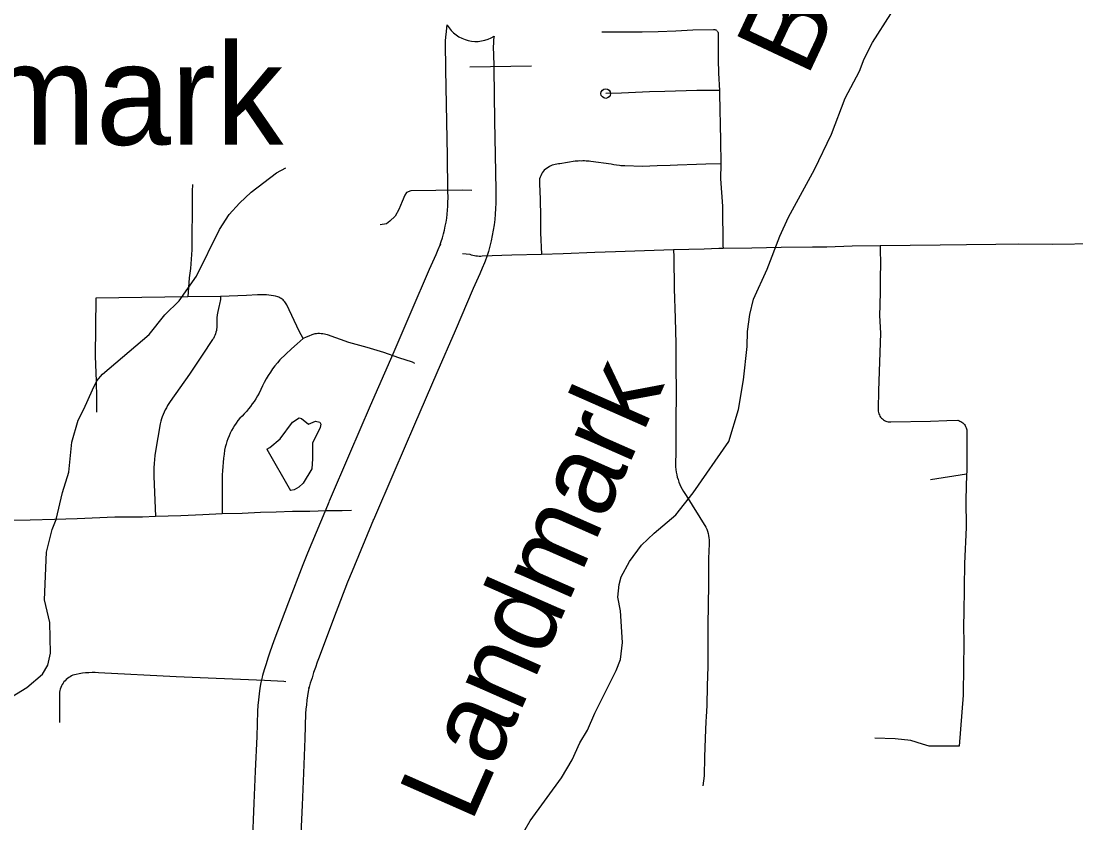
# Model space of a CAD drawing. Extents: x -19 to 366, y -4 to 359.
# Drawn here: x 152.307 to 153.352, y 181.159 to 181.952 of the extents above; entities that cross this region are included whole.
import ezdxf

# ---------------------------------------------------------------- set-up
doc = ezdxf.new("R2010")
doc.units = 0
for name, color, linetype in [('Level 10', 7, 'Continuous'), ('Level 24', 7, 'Continuous'), ('Level 31', 7, 'Continuous'), ('Level 35', 7, 'Continuous'), ('Level 60', 7, 'Continuous')]:
    doc.layers.add(name, color=color, linetype=linetype)

msp = doc.modelspace()

# ---------------------------------------------------------------- linework, layer by layer
at = {"layer": 'Level 10'}
for p, q in [((152.7752, 181.9088), (152.7752, 181.9088)), ((152.7772, 181.7846), (152.7772, 181.7846)), ((152.7225, 181.7313), (152.7218, 181.7296)), ((152.7667, 181.7144), (152.766, 181.7127)), ((152.7189, 181.6039), (152.7189, 181.6039)), ((152.6562, 181.4589), (152.6351, 181.4076)), ((152.6561, 181.4586), (152.6562, 181.4589)), ((152.6351, 181.4076), (152.6351, 181.4076)), ((152.5462, 181.3029), (152.5466, 181.3048)), ((152.5921, 181.2915), (152.5926, 181.2934))]:
    msp.add_line(p, q, dxfattribs=at)
for points in [[(152.7279, 181.9078), (152.7275, 181.9272), (152.7276, 181.932), (152.7279, 181.9366), (152.7283, 181.9413), (152.7289, 181.9458), (152.7292, 181.9482)], [(152.7755, 181.9371), (152.7754, 181.9361), (152.7751, 181.9331), (152.7749, 181.9299), (152.7748, 181.927), (152.7752, 181.9088)], [(152.7299, 181.784), (152.7294, 181.8187), (152.7287, 181.8524), (152.7279, 181.9042), (152.7279, 181.9077)], [(152.7752, 181.9088), (152.7753, 181.905), (152.776, 181.8533), (152.7768, 181.8196), (152.7772, 181.7846)], [(152.7218, 181.7296), (152.7232, 181.7338), (152.7245, 181.7376), (152.7255, 181.7414), (152.7265, 181.7452), (152.7273, 181.7491), (152.728, 181.7531), (152.7287, 181.757), (152.7291, 181.761), (152.7295, 181.765), (152.7298, 181.7689), (152.7299, 181.7729), (152.73, 181.777), (152.7299, 181.784)], [(152.7772, 181.7846), (152.7773, 181.7772), (152.7773, 181.7719), (152.7771, 181.7665), (152.7767, 181.7611), (152.7762, 181.7558), (152.7756, 181.7504), (152.7747, 181.7451), (152.7737, 181.7399), (152.7726, 181.7346), (152.7713, 181.7294), (152.7699, 181.7241), (152.7683, 181.7191), (152.7667, 181.7144)], [(152.6755, 181.6228), (152.6935, 181.6642), (152.7115, 181.7066), (152.7181, 181.7209), (152.7202, 181.7259), (152.7225, 181.7313)], [(152.766, 181.7127), (152.7638, 181.7076), (152.7615, 181.7019), (152.7547, 181.6874), (152.737, 181.6455), (152.7189, 181.6039)], [(152.6126, 181.4773), (152.6327, 181.5242), (152.6533, 181.5717), (152.6755, 181.6228)], [(152.7189, 181.6039), (152.6967, 181.5528), (152.6762, 181.5055), (152.6561, 181.4586)], [(152.5913, 181.4257), (152.6125, 181.477)], [(152.5466, 181.3048), (152.5483, 181.3105), (152.5501, 181.3163), (152.5519, 181.322), (152.5539, 181.3278), (152.5559, 181.3335), (152.5579, 181.3391), (152.5722, 181.3774), (152.5866, 181.4144), (152.5913, 181.4257)], [(152.6351, 181.4076), (152.6306, 181.3967), (152.6165, 181.3605), (152.6023, 181.3227), (152.6005, 181.3176), (152.5987, 181.3124), (152.5969, 181.3073), (152.5953, 181.3021), (152.5936, 181.2968), (152.5921, 181.2915)], [(152.5278, 181.0853), (152.5331, 181.1033), (152.5343, 181.111), (152.5355, 181.1252), (152.5365, 181.1365), (152.5381, 181.1782), (152.5395, 181.2098), (152.5409, 181.244), (152.5417, 181.2691), (152.5421, 181.2748), (152.5426, 181.2805), (152.5432, 181.2862), (152.5441, 181.292), (152.5451, 181.2976), (152.5462, 181.3029)], [(152.5926, 181.2934), (152.5916, 181.2887), (152.5908, 181.2843), (152.5902, 181.28), (152.5897, 181.2756), (152.5893, 181.2712), (152.589, 181.2668), (152.5882, 181.2423), (152.5868, 181.2078), (152.5854, 181.1762), (152.5837, 181.1336), (152.5827, 181.1213), (152.5814, 181.1052), (152.5793, 181.0928), (152.5732, 181.072)]]:
    msp.add_lwpolyline(points, dxfattribs=at)
msp.add_arc((152.7578, 181.9652), 0.0333, 210.8117, 302.1366, dxfattribs=at)
at = {"layer": 'Level 31'}
msp.add_line((152.7516, 181.9069), (152.8125, 181.9077), dxfattribs=at)
for points in [[(152.9961, 181.9426), (152.9956, 181.9429), (152.9951, 181.9432), (152.9946, 181.9434), (152.994, 181.9435), (152.9934, 181.9435), (152.9928, 181.9435), (152.9723, 181.943), (152.9554, 181.9422), (152.9379, 181.9415), (152.9221, 181.9412), (152.9073, 181.9409), (152.8823, 181.9409)], [(152.9961, 181.9426), (152.9965, 181.9422), (152.9969, 181.9417), (152.9971, 181.9411), (152.9973, 181.9406), (152.9974, 181.94), (152.9974, 181.914), (152.9978, 181.9006), (152.9986, 181.8835)], [(152.9986, 181.8835), (152.9762, 181.8832), (152.9446, 181.8825), (152.9294, 181.8821), (152.9017, 181.8806), (152.8861, 181.8803)], [(152.9986, 181.8835), (152.9988, 181.8801), (152.9996, 181.834), (153.0002, 181.8108)], [(153.0002, 181.8108), (152.9853, 181.8106), (152.976, 181.8101), (152.9571, 181.8093), (152.9498, 181.809), (152.9369, 181.8087), (152.9226, 181.8081), (152.9051, 181.8089), (152.9037, 181.8088), (152.901, 181.8089), (152.8997, 181.809), (152.8969, 181.8093), (152.8942, 181.8097), (152.8915, 181.8103), (152.8712, 181.8132), (152.8696, 181.8133), (152.8681, 181.8135), (152.8666, 181.8135), (152.865, 181.8136), (152.8635, 181.8136), (152.8619, 181.8135), (152.8604, 181.8136), (152.8589, 181.8135), (152.8573, 181.8134), (152.8558, 181.8133), (152.8407, 181.8109), (152.8392, 181.8107), (152.8377, 181.8105), (152.8362, 181.8102), (152.8347, 181.8098), (152.8332, 181.8093), (152.8304, 181.8081), (152.829, 181.8073), (152.8265, 181.8056), (152.8253, 181.8045), (152.8242, 181.8033), (152.8232, 181.802), (152.8228, 181.8013)], [(153.0002, 181.8108), (152.9999, 181.796), (153.0016, 181.769), (153.0021, 181.7296), (153.0023, 181.7272)], [(152.8228, 181.8013), (152.8224, 181.8005), (152.8217, 181.799), (152.8211, 181.7975), (152.8207, 181.7959), (152.8205, 181.7942), (152.8204, 181.7926), (152.8206, 181.7909), (152.8213, 181.7758), (152.8216, 181.7584), (152.8216, 181.7426), (152.8226, 181.7215)], [(152.4769, 181.7904), (152.4768, 181.7838), (152.4767, 181.7762), (152.4768, 181.7686), (152.4764, 181.7348), (152.4764, 181.7302), (152.4763, 181.7256), (152.4761, 181.721), (152.4758, 181.7164), (152.4754, 181.7118), (152.4749, 181.7072), (152.4744, 181.7027), (152.4737, 181.6981), (152.4725, 181.6793)], [(152.7535, 181.7843), (152.7439, 181.7848), (152.7179, 181.7843), (152.6933, 181.784), (152.6889, 181.7825), (152.6871, 181.7799), (152.6845, 181.7736), (152.6812, 181.7655), (152.6775, 181.7589), (152.6723, 181.7539), (152.6689, 181.7513), (152.6627, 181.7504)], [(152.8226, 181.7215), (152.844, 181.7221), (152.8752, 181.7234), (152.8957, 181.724), (152.9531, 181.7259)], [(152.9531, 181.7259), (152.9836, 181.7266), (152.9982, 181.7272), (153.0023, 181.7272)], [(152.9531, 181.7259), (152.9534, 181.7184), (152.9539, 181.6871), (152.9549, 181.6581), (152.9555, 181.6327), (152.9556, 181.608), (152.9558, 181.5877), (152.9554, 181.5524), (152.9554, 181.5209), (152.9551, 181.5184), (152.9551, 181.5158), (152.9551, 181.5133), (152.9553, 181.5108), (152.9555, 181.5082), (152.9559, 181.5057), (152.9564, 181.5032), (152.957, 181.5007), (152.9578, 181.4983), (152.9586, 181.4959), (152.9596, 181.4935), (152.9606, 181.4912), (152.9618, 181.4889), (152.9631, 181.4867), (152.9644, 181.4846), (152.9659, 181.4825), (152.9853, 181.4512), (152.9861, 181.4492), (152.9868, 181.4472), (152.9874, 181.4451), (152.9879, 181.443), (152.9882, 181.4408), (152.9885, 181.4387), (152.9886, 181.4365), (152.9886, 181.4343), (152.9884, 181.4322), (152.9881, 181.43), (152.9878, 181.4176), (152.988, 181.3946), (152.9872, 181.3543), (152.9872, 181.336), (152.9871, 181.3133), (152.9866, 181.2942), (152.9862, 181.2749), (152.9854, 181.2637), (152.9852, 181.259), (152.9845, 181.2426), (152.984, 181.2236), (152.9837, 181.2051), (152.9824, 181.1954)], [(153.0023, 181.7272), (153.0306, 181.7278), (153.0599, 181.7284), (153.0907, 181.7285), (153.105, 181.7288), (153.1301, 181.7295), (153.1579, 181.7299)], [(153.1579, 181.7299), (153.1578, 181.7252), (153.1583, 181.7128), (153.1579, 181.6972), (153.1578, 181.6844), (153.1576, 181.6709), (153.1573, 181.6608), (153.1582, 181.6433), (153.1562, 181.5862), (153.1558, 181.5684), (153.1558, 181.5672), (153.1559, 181.5659), (153.1561, 181.5646), (153.1565, 181.5634), (153.157, 181.5623), (153.1576, 181.5611), (153.1583, 181.5601), (153.1591, 181.5591), (153.1601, 181.5583), (153.1611, 181.5575), (153.1622, 181.5568), (153.1633, 181.5563), (153.1645, 181.5559), (153.1658, 181.5556), (153.167, 181.5554), (153.1683, 181.5554), (153.2076, 181.5563), (153.2238, 181.5569), (153.2346, 181.5571), (153.2357, 181.5568), (153.2368, 181.5563), (153.2378, 181.5558), (153.2388, 181.5552), (153.2397, 181.5544), (153.2405, 181.5536), (153.2413, 181.5527), (153.2419, 181.5518), (153.2424, 181.5508), (153.2429, 181.5497), (153.2433, 181.5486), (153.2435, 181.5475), (153.2437, 181.5463), (153.2437, 181.5451), (153.2435, 181.5061), (153.2434, 181.5037)], [(153.1579, 181.7299), (153.2172, 181.7307), (153.2432, 181.7309), (153.2722, 181.7314), (153.295, 181.7315), (153.3284, 181.7314), (153.3725, 181.7318)], [(152.7442, 181.722), (152.7515, 181.7214), (152.753, 181.7208), (152.7545, 181.7204), (152.7561, 181.72), (152.7576, 181.7197), (152.7592, 181.7196), (152.7607, 181.7195), (152.7623, 181.7195), (152.7639, 181.7197), (152.7933, 181.7207), (152.8226, 181.7215)], [(152.3813, 181.678), (152.3807, 181.6203), (152.3815, 181.5958), (152.382, 181.5792), (152.3818, 181.5649)], [(152.4725, 181.6793), (152.3813, 181.678)], [(152.5046, 181.6796), (152.5047, 181.678), (152.5046, 181.6765), (152.5044, 181.675), (152.5042, 181.6735), (152.5038, 181.672), (152.5033, 181.6706), (152.5026, 181.6676), (152.502, 181.6646), (152.5014, 181.6615), (152.501, 181.6585), (152.501, 181.6522), (152.501, 181.6505), (152.501, 181.6489), (152.5008, 181.6473), (152.5006, 181.6457), (152.5002, 181.6441), (152.4997, 181.6426), (152.4992, 181.641), (152.4985, 181.6396), (152.4977, 181.6381), (152.4969, 181.6368), (152.4867, 181.6216), (152.4741, 181.6026), (152.455, 181.5755), (152.4536, 181.5735), (152.4523, 181.5715), (152.4511, 181.5694), (152.4499, 181.5673), (152.4489, 181.5651), (152.4479, 181.5628), (152.4471, 181.5606), (152.4463, 181.5583), (152.4456, 181.556), (152.445, 181.5536), (152.4404, 181.5264), (152.4398, 181.5223), (152.4393, 181.5182), (152.439, 181.5141), (152.4388, 181.5099), (152.4387, 181.5058), (152.4388, 181.5017), (152.4405, 181.4618)], [(152.5046, 181.6796), (152.4725, 181.6793)], [(152.5866, 181.6379), (152.5825, 181.6451), (152.5703, 181.6712), (152.5697, 181.6723), (152.569, 181.6733), (152.5683, 181.6743), (152.5675, 181.6752), (152.5666, 181.6761), (152.5657, 181.6769), (152.5647, 181.6776), (152.5636, 181.6782), (152.5625, 181.6787), (152.5614, 181.6792), (152.5592, 181.6797), (152.5571, 181.6802), (152.5549, 181.6806), (152.5527, 181.6809), (152.5504, 181.681), (152.5482, 181.6811), (152.5415, 181.6811), (152.5303, 181.6805), (152.5046, 181.6796)], [(152.6972, 181.6133), (152.6948, 181.6146), (152.6814, 181.6187), (152.6665, 181.624), (152.6499, 181.6291), (152.6317, 181.6341), (152.6107, 181.6416), (152.6091, 181.642), (152.6076, 181.6423), (152.606, 181.6426), (152.6044, 181.6427), (152.6028, 181.6428), (152.6012, 181.6428), (152.5997, 181.6427), (152.5981, 181.6426), (152.5951, 181.6415), (152.5922, 181.6404), (152.5894, 181.6392), (152.5866, 181.6379)], [(152.5866, 181.6379), (152.5807, 181.6328), (152.575, 181.6276), (152.5693, 181.6224), (152.5636, 181.617), (152.5611, 181.614), (152.5586, 181.611), (152.5563, 181.6078), (152.5541, 181.6046), (152.5519, 181.6013), (152.5499, 181.5979), (152.548, 181.5945), (152.5462, 181.591), (152.5446, 181.5875), (152.543, 181.5838), (152.5415, 181.5811), (152.5398, 181.5784), (152.538, 181.5757), (152.5362, 181.5732), (152.5343, 181.5706), (152.5323, 181.5682), (152.5303, 181.5658), (152.5281, 181.5634), (152.526, 181.5612), (152.5237, 181.559), (152.5219, 181.5567), (152.5202, 181.5543), (152.5186, 181.5519), (152.5171, 181.5494), (152.5157, 181.5468), (152.5144, 181.5442), (152.5132, 181.5415), (152.5121, 181.5388), (152.5111, 181.5361), (152.5102, 181.5333), (152.5094, 181.5304), (152.5088, 181.5276), (152.5082, 181.5235), (152.5077, 181.5194), (152.5072, 181.5153), (152.5069, 181.5112), (152.5066, 181.507), (152.5065, 181.5029), (152.5064, 181.4988), (152.5064, 181.4946), (152.5064, 181.4646)], [(153.2434, 181.5037), (153.2428, 181.4784), (153.2429, 181.4508), (153.2414, 181.4152), (153.2409, 181.3915), (153.2406, 181.366), (153.2402, 181.3548), (153.2405, 181.3353), (153.2402, 181.314), (153.24, 181.285), (153.236, 181.2344), (153.2064, 181.2344), (153.1998, 181.2365), (153.1882, 181.2403), (153.1727, 181.2418), (153.1527, 181.2424)], [(153.2434, 181.5037), (153.2077, 181.4981)], [(152.5064, 181.4646), (152.4872, 181.4635), (152.4654, 181.4626), (152.4405, 181.4618)], [(152.6344, 181.4679), (152.625, 181.4673), (152.6097, 181.4673), (152.593, 181.4668), (152.576, 181.4666), (152.5598, 181.4662), (152.5442, 181.4659), (152.5263, 181.4649), (152.5064, 181.4646)], [(152.4405, 181.4618), (152.4276, 181.4611), (152.4, 181.4613), (152.3629, 181.4595), (152.3402, 181.459), (152.3162, 181.4581), (152.2833, 181.4575), (152.2643, 181.4575), (152.2462, 181.4571), (152.2225, 181.4566), (152.1909, 181.4554), (152.18, 181.455), (152.1691, 181.4548), (152.147, 181.454), (152.1213, 181.4528), (152.0899, 181.4518)], [(152.5694, 181.2981), (152.5673, 181.2986), (152.5484, 181.2995), (152.4609, 181.3031), (152.3839, 181.3071), (152.3807, 181.3073), (152.3775, 181.3073), (152.3743, 181.3072), (152.3711, 181.307), (152.368, 181.3067), (152.3648, 181.3062), (152.3617, 181.3055), (152.3586, 181.3047), (152.3571, 181.3041), (152.3557, 181.3033), (152.3544, 181.3025), (152.3531, 181.3015), (152.3519, 181.3005), (152.3508, 181.2993), (152.3497, 181.2981), (152.3488, 181.2968), (152.348, 181.2955), (152.3472, 181.2941), (152.3466, 181.2926), (152.3461, 181.2911), (152.3457, 181.2895), (152.3453, 181.288), (152.3453, 181.2581)]]:
    msp.add_lwpolyline(points, dxfattribs=at)
msp.add_circle((152.8861, 181.8803), 0.00473, dxfattribs=at)
at = {"layer": 'Level 35'}
for points in [[(153.046, 181.7065), (153.0586, 181.7392), (153.0671, 181.7581), (153.0929, 181.8053), (153.1096, 181.8402), (153.1233, 181.8759), (153.1372, 181.9026), (153.1421, 181.9146), (153.1503, 181.9307), (153.1683, 181.9591)], [(152.3781, 181.5871), (152.3821, 181.5959), (152.3878, 181.6027), (152.434, 181.6419), (152.4497, 181.6613), (152.4637, 181.6751), (152.4808, 181.6995), (152.5037, 181.7459), (152.5133, 181.7605), (152.5235, 181.7719), (152.535, 181.7829), (152.56, 181.802), (152.5694, 181.8069)], [(152.7916, 181.1263), (152.8113, 181.1606), (152.8423, 181.2033), (152.8528, 181.221), (152.8604, 181.2378), (152.8679, 181.2505), (152.8752, 181.2671), (152.8965, 181.3093), (152.9006, 181.3204), (152.9028, 181.3373), (152.9007, 181.3684), (152.8981, 181.382), (152.8994, 181.3944), (152.9013, 181.4022), (152.9096, 181.4173), (152.9216, 181.4333), (152.9342, 181.4453), (152.9554, 181.4634), (152.9726, 181.4852), (153.008, 181.5361), (153.0174, 181.5676), (153.0225, 181.5969), (153.0262, 181.63), (153.0265, 181.6448), (153.0287, 181.6616), (153.0325, 181.677), (153.046, 181.7065)], [(152.2862, 181.2766), (152.3131, 181.2925), (152.3286, 181.3059), (152.3339, 181.3147), (152.3365, 181.3267), (152.3356, 181.3569), (152.3306, 181.3795), (152.3325, 181.4266), (152.338, 181.4489), (152.3419, 181.4589), (152.3484, 181.4854), (152.3547, 181.5056), (152.3575, 181.5355), (152.3637, 181.5572), (152.3694, 181.568), (152.3781, 181.5871)], [(152.5505, 181.5285), (152.5537, 181.5301), (152.5638, 181.5387), (152.576, 181.555), (152.5827, 181.5595), (152.585, 181.5588), (152.5919, 181.5532), (152.5987, 181.5562), (152.603, 181.555), (152.604, 181.5531), (152.6035, 181.5498), (152.5957, 181.5343), (152.5958, 181.5188), (152.5952, 181.5091), (152.5864, 181.4947), (152.5823, 181.4908), (152.5778, 181.4883), (152.5741, 181.4874)], [(152.5505, 181.5285), (152.5741, 181.4874)]]:
    msp.add_lwpolyline(points, dxfattribs=at)
at = {"layer": 'Level 60'}
for points in [[(154.1159, 1.8709), (153.9063, 10.4874), (153.696, 19.1041), (153.485, 27.7209), (153.2733, 36.3378), (153.0608, 44.9549), (152.8476, 53.5721), (152.6337, 62.1894), (152.419, 70.8069), (152.2036, 79.4245), (151.9875, 88.0422), (151.7707, 96.6601), (151.5531, 105.2782), (151.3348, 113.8963), (151.1158, 122.5147), (150.8961, 131.1331), (150.6757, 139.7517), (150.4545, 148.3704), (150.2326, 156.9893), (150.0101, 165.6083), (149.7867, 174.2275), (149.5627, 182.8468), (149.338, 191.4662), (149.1125, 200.0858), (148.8864, 208.7055), (148.6595, 217.3254), (148.4319, 225.9454), (148.2037, 234.5655), (147.9747, 243.1858), (147.745, 251.8063), (147.5146, 260.4269), (147.2835, 269.0476), (147.0517, 277.6685), (146.8191, 286.2895), (146.5859, 294.9106), (146.352, 303.5319), (146.1174, 312.1534), (145.8821, 320.775), (145.6461, 329.3967), (145.4094, 338.0186), (145.172, 346.6406)], [(0, 180.8999), (7.1228, 180.9044), (14.2457, 180.9176), (21.3685, 180.9397), (28.4912, 180.9706), (35.614, 181.0103), (42.7366, 181.0589), (49.8592, 181.1163), (56.9818, 181.1825), (64.1042, 181.2575), (71.2266, 181.3414), (78.3488, 181.4341), (85.4709, 181.5357), (92.5929, 181.646), (99.7147, 181.7652), (106.8364, 181.8933), (113.9579, 182.0301), (121.0793, 182.1758), (128.2005, 182.3303), (135.3214, 182.4936), (142.4422, 182.6658), (149.5627, 182.8468), (156.683, 183.0366), (163.8031, 183.2352), (170.9229, 183.4427), (178.0425, 183.659), (185.1617, 183.8841), (192.2807, 184.1181), (199.3994, 184.3608), (206.5178, 184.6124), (213.6359, 184.8728), (220.7537, 185.1421), (227.8711, 185.4201), (234.9881, 185.707), (242.1048, 186.0027), (249.2212, 186.3073), (256.3371, 186.6206), (263.4526, 186.9428), (270.5678, 187.2738), (277.6825, 187.6136), (284.7968, 187.9622), (291.9107, 188.3197), (299.0241, 188.6859), (306.1371, 189.061), (313.2495, 189.4449), (320.3615, 189.8377), (327.4731, 190.2392), (334.5841, 190.6495), (341.6946, 191.0687)], [(0, 172.2839), (7.1335, 172.2883), (14.267, 172.3015), (21.4005, 172.3236), (28.5339, 172.3544), (35.6673, 172.3941), (42.8006, 172.4426), (49.9339, 172.4999), (57.0671, 172.566), (64.2002, 172.6409), (71.3332, 172.7246), (78.4661, 172.8172), (85.5989, 172.9186), (92.7315, 173.0287), (99.8641, 173.1477), (106.9964, 173.2755), (114.1286, 173.4122), (121.2606, 173.5576), (128.3925, 173.7119), (135.5241, 173.8749), (142.6555, 174.0468), (149.7867, 174.2275), (156.9177, 174.417), (164.0485, 174.6153), (171.179, 174.8224), (178.3092, 175.0383), (185.4392, 175.2631), (192.5688, 175.4966), (199.6982, 175.739), (206.8273, 175.9902), (213.9561, 176.2502), (221.0845, 176.5189), (228.2126, 176.7965), (235.3404, 177.083), (242.4677, 177.3782), (249.5948, 177.6822), (256.7214, 177.995), (263.8476, 178.3167), (270.9735, 178.6471), (278.0989, 178.9863), (285.2239, 179.3344), (292.3485, 179.6912), (299.4726, 180.0569), (306.5963, 180.4314), (313.7195, 180.8146), (320.8422, 181.2067), (327.9644, 181.6076), (335.0862, 182.0172), (342.2074, 182.4357)]]:
    msp.add_spline(points, degree=3, dxfattribs=at)

# ---------------------------------------------------------------- texts
at = {"layer": 'Level 24'}
msp.add_text('Landmark', height=0.1, dxfattribs=at).set_placement((151.9724, 181.8296))
at = {"layer": 'Level 35'}
for s, rotation, p in [('Br.', 64.9022, (153.0853, 181.8952)), ('Landmark', 66.218, (152.7528, 181.1574))]:
    msp.add_text(s, height=0.08, rotation=rotation, dxfattribs=at).set_placement(p)

doc.saveas('drawing.dxf')
